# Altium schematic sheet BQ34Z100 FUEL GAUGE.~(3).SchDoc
size A3; SheetNumber: 13; SheetTotal: 14
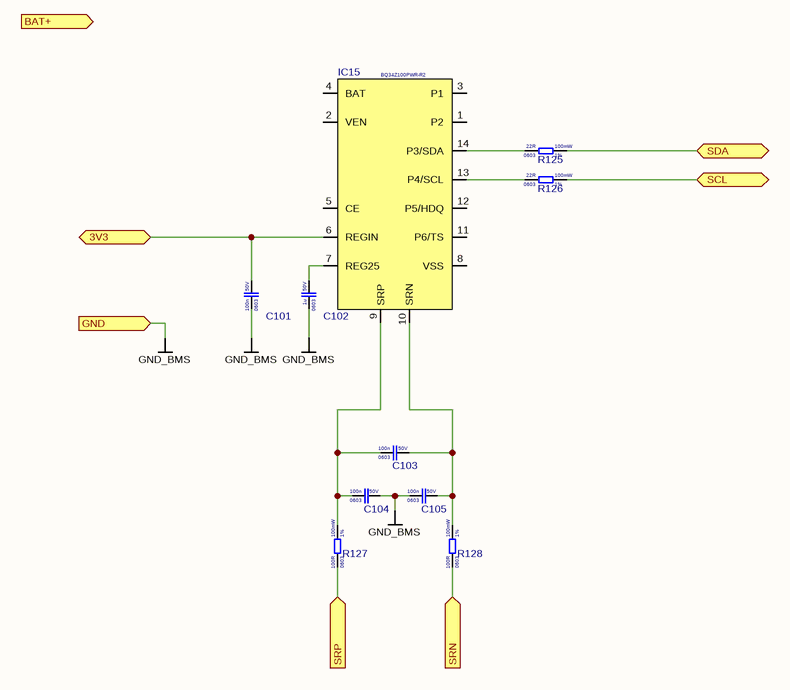
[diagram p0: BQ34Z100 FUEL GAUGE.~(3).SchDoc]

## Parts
C101  Voltage Rating: 50V  Case Code (Imperial): 0603  Capacitance: 100n  [CAP 0603]  (hidden comment: CC0603KRX7R9BB104)
C102  Voltage Rating: 50V  Case Code (Imperial): 0603  Capacitance: 1u  [CAP 0603]  (hidden comment: CL10A105KB8NNNC)
C103  Voltage Rating: 50V  Case Code (Imperial): 0603  Capacitance: 100n  [CAP 0603]  (hidden comment: CC0603KRX7R9BB104)
C104  Voltage Rating: 50V  Case Code (Imperial): 0603  Capacitance: 100n  [CAP 0603]  (hidden comment: CC0603KRX7R9BB104)
C105  Voltage Rating: 50V  Case Code (Imperial): 0603  Capacitance: 100n  [CAP 0603]  (hidden comment: CC0603KRX7R9BB104)
IC15  BQ34Z100PWR-R2  [TSSOP-14]
R125  Resistance Tolerance: 1%  Resistance: 22R  Power Rating: 100mW  Case Code (Imperial): 0603  [RES_0603]  (hidden comment: 0603WAF220JT5E)
R126  Resistance Tolerance: 1%  Resistance: 22R  Power Rating: 100mW  Case Code (Imperial): 0603  [RES_0603]  (hidden comment: 0603WAF220JT5E)
R127  Resistance Tolerance: 1%  Resistance: 100R  Power Rating: 100mW  Case Code (Imperial): 0603  [RES_0603]  (hidden comment: 0603WAF1000T5E)
R128  Resistance Tolerance: 1%  Resistance: 100R  Power Rating: 100mW  Case Code (Imperial): 0603  [RES_0603]  (hidden comment: 0603WAF1000T5E)

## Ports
3V3 (bidir, see BMS[4C], 5V to 3V3 LDO[5B]), BAT+ (in, see BMS[4D], BAT+ to 5V1 STEP-DOWN[3B], BMS[1A], BQ76952 BMS[1A]), GND (in, see BMS[4D], 5V to 3V3 LDO[3B], BAT+ to 5V1 STEP-DOWN[3C], BQ76952 BMS[1D], MCU[1C]), SCL (bidir, see BMS[4C], BMS[8C], BQ76952 BMS[7C], MCU[1B]), SDA (bidir, see BMS[4C], BMS[8C], BQ76952 BMS[7C], MCU[1B]), SRN (in, see BMS[4D], BQ76952 BMS[5D]), SRP (in, see BMS[4D], BQ76952 BMS[5D])

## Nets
GND_BMS: C101.1 C102.1 C104.2 C105.1 ; port GND
3V3: C101.2 IC15.6(REGIN) ; port 3V3
SCL: R126.2 ; port SCL
SDA: R125.2 ; port SDA
SRN: R128.1 ; port SRN
SRP: R127.1 ; port SRP
NetC102_2: C102.2 IC15.7(REG25)
NetC103_1: C103.1 C104.1 IC15.9(SRP) R127.2
NetC103_2: C103.2 C105.2 IC15.10(SRN) R128.2
NetIC15_13: IC15.13(P4/SCL) R126.1
NetIC15_14: IC15.14(P3/SDA) R125.1

Not connected (* = marked no-connect by the designer): IC15 1(P2) 2(VEN) 3(P1) 4(BAT) 5(CE) 8(VSS) 11(P6/TS) 12(P5/HDQ)

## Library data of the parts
C101 C103-C105 = CC0603KRX7R9BB104: Cap 100nF 50V 0603 X7R; Manufacturer: Yageo
C102 = CL10A105KB8NNNC: Cap 1uF 50V 0603 X5R; Manufacturer: Samsung
IC15 = BQ34Z100PWR-R2: Fuel gauge; Manufacturer: Texas Instruments
R125 R126 = 0603WAF220JT5E: Res 22R 0603 1% 100mW 75V; Manufacturer: Uni-Royal
R127 R128 = 0603WAF1000T5E: Res 100R 0603 1% 100mW 75V; Manufacturer: Uni-Royal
